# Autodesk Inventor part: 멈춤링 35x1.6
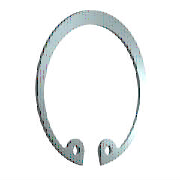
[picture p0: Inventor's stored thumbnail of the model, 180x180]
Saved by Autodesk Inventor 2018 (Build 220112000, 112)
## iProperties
IsCustomPart: 1
Created: 2012-02
Part Number: 멈춤링 35x1.6
Material: 강철, 연강
Description: 리테이닝 링(C형)
Document SubType Name: Modeling
Standard: KS B 1336
Designer: mduedu
Standards Organization: KS
Language: ko-KR
Size Designation: 35x1.6
Categories: <MemberInstance><Categories><Category DisplayName="샤프트 부품" InternalName="7f7aeb1f-a693-4053-b835-cee3144e0d98" Mnemonic="SHFT"><Category DisplayName="써클립" Inter
Density: 1 g/cm^3
Appearance: 파란색 - 벽 페인트 - 광택
Author: mduedu
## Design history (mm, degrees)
sketch "스케치1"
  geometry: L1 (0, 15.113)-(0, -73.177) reference; L2 (-45.5, 0)-(45.5, 0) reference; L3 (-4.964, 1)-(1.502, 1); L4 (0, -2.5)-(-5.307, -2.5); L5 (0, -17.5)-(-8.583, -33.888); L6 (-8.583, -33.888)-(-21.772, -26.981); L7 (-7.377, -31.585)-(-17.631, -26.214); L8 (-5.162, -32.745)-(-6.29, -34.898); L9 (5.162, -32.745)-(6.29, -34.898); C1 r 1.25 at (-7.377, -31.585); C2 r 1.25 at (7.377, -31.585); A1 r 15.875 centre (0, -18.375) between (11.82, -28.972) and (-11.82, -28.972); A2 r 18.5 centre (0, -17.5) between (6.29, -34.898) and (-6.29, -34.898); A3 r 2.5 centre (-7.377, -31.585) between (-5.162, -32.745) and (-8.668, -29.444); A4 r 2.5 centre (-9.959, -27.303) between (-11.82, -28.972) and (-8.668, -29.444); A5 r 2.5 centre (9.959, -27.303) between (8.668, -29.444) and (11.82, -28.972); A6 r 2.5 centre (7.377, -31.585) between (8.668, -29.444) and (5.162, -32.745); 3 further points
  constraints: 15 point on circle, 14 end point, 9 symmetric about line, 8 centre point, 6 tangent, 4 coincident, 4 point on line, 3 perpendicular, 1 parallel, 4 other
  dimensions: "d8" = 0.875 distance of A1.centre L5.start (= 0.25 x SRB1); "d38" = 3.5 distance between parallel lines of L4 L3 (= SRB1); "d39" = 17.5 distance from line of L5.start L2 (= 0.5 x WD); "d43" = 18.5 radius of A2 (= 0.5 x ND); "d45" = 2.6 distance between parallel lines of L7 L6 (= 0.5 x SRB2); "d46" = 2.5 radius of A4 (= SD5); "d47" = 6.29 distance from line of L1 L8.end (= 0.17 x ND); "d48" = 2.5 diameter of C1 (= SD5); "d49" = 2.5 radius of A3 (= SD5)
extrude "본체" new body sketch "스케치1" distance "d2" = 1.6 (= SD); taper "d3" = 0 deg
workaxis "Work Axis1"
workaxis "Work Axis2"
workplane "Work Plane1"
body "Solid1"
other parameters: "WD" = 35 [user parameter; used in 3 equation terms], "SD" = 1.6 [user parameter; used in 1 equation term], "SRB1" = 3.5 [user parameter; used in 2 equation terms], "ND" = 37 [user parameter; used in 2 equation terms], "SRB2" = 5.2 [user parameter; used in 1 equation term], "SD5" = 2.5 [user parameter; used in 3 equation terms], "d50" = 0, "d51" = 0, "d52" = 0, "d53" = 0, "WDMIN" = 34 [user parameter], "SD6" = 37.8 [user parameter], "WDMAX" = 35 (= WD) [user parameter], "NND" = 35 (= WD) [user parameter]
